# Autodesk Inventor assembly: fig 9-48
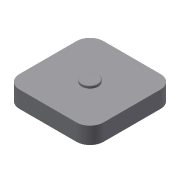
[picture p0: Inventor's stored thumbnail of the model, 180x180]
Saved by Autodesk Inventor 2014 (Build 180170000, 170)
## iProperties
Created: 2013-07
Part Number: fig 9-48
Document SubType Name: Assembly
Designer: CADCIM
Author: CADCIM
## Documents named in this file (3)
- E:\APS\Autodesk Inventor 2014-Project\inventor_2014_partfiles\Inventor_2014_prt\c09_Inv_2014_prt\c09_inv_2014_prt\fig 9-48.iam
- E:\APS\c09partfile\fig 9-47_1.ipt
- E:\APS\c09partfile\fig 9-47_2.ipt
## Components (2 placed, 2 different names)
1. fig 9-47_1:1 — Planar:1
2. fig 9-47_2:1 — Planar:1
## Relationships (1: PlanarJoint 1)
- Planar:1: fig 9-47_1:1 ↔ fig 9-47_2:1
